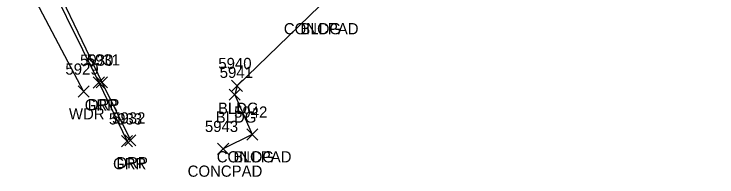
# Model space of a CAD drawing. Extents: x 1618146 to 1620418, y 640749 to 641927.
# Drawn here: x 1619963.1 to 1620088.9, y 641107.6 to 641136.7 of the extents above; entities that cross this region are included whole.
import ezdxf

# ---------------------------------------------------------------- set-up
doc = ezdxf.new("R2010")
doc.units = 0
for name, color, linetype in [('L_A', 7, 'Continuous'), ('L_I', 7, 'Continuous'), ('L_TIC', 7, 'Continuous'), ('LAWA', 7, 'Continuous'), ('LBC', 7, 'Continuous'), ('LS', 7, 'Continuous'), ('R_A', 7, 'Continuous'), ('R_I', 7, 'Continuous'), ('R_TIC', 7, 'Continuous'), ('RDP', 7, 'Continuous'), ('RGR', 7, 'Continuous')]:
    doc.layers.add(name, color=color, linetype=linetype)

msp = doc.modelspace()

# ---------------------------------------------------------------- linework, layer by layer
at = {"layer": 'L_TIC'}
for points in [[(1620001.99, 641122.9), (1620003.99, 641124.9)], [(1620003.99, 641122.9), (1620001.99, 641124.9)], [(1619974.53, 641121.9), (1619976.53, 641123.9)], [(1619976.53, 641121.9), (1619974.53, 641123.9)], [(1620001.58, 641121.32), (1620003.58, 641123.32)], [(1620003.58, 641121.32), (1620001.58, 641123.32)], [(1620004.73, 641114.22), (1620006.73, 641116.22)], [(1620006.73, 641114.22), (1620004.73, 641116.22)], [(1620004.73, 641114.22), (1620006.73, 641116.22)], [(1620006.73, 641114.22), (1620004.73, 641116.22)], [(1619999.5, 641111.66), (1620001.5, 641113.66)], [(1620001.5, 641111.66), (1619999.5, 641113.66)]]:
    msp.add_lwpolyline(points, dxfattribs=at)
at = {"layer": 'LAWA'}
msp.add_lwpolyline([(1620011.76, 641198.79), (1619992.67, 641182.34), (1619977.79, 641170.88), (1619968.52, 641161.58), (1619963.08, 641155.85), (1619963.66, 641145.43), (1619975.53, 641122.9)], dxfattribs=at)
at = {"layer": 'LBC'}
msp.add_lwpolyline([(1620182.25, 641113.36), (1620138.87, 641158.88), (1620119.63, 641179.08), (1620099.14, 641200.68), (1620061.44, 641164.75), (1620044.43, 641182.84), (1620044.17, 641182.77), (1620022.6, 641162.29), (1620014.93, 641155.19), (1620024.72, 641144.88), (1620017.73, 641138.11), (1620002.99, 641123.9), (1620002.58, 641122.32), (1620005.73, 641115.22)], dxfattribs=at)
at = {"layer": 'LS'}
msp.add_lwpolyline([(1620005.73, 641115.22), (1620000.5, 641112.66)], dxfattribs=at)
at = {"layer": 'R_TIC'}
for points in [[(1619977.24, 641123.49), (1619979.24, 641125.49)], [(1619979.24, 641123.49), (1619977.24, 641125.49)], [(1619977.8, 641123.54), (1619979.8, 641125.54)], [(1619979.8, 641123.54), (1619977.8, 641125.54)], [(1619982.31, 641113), (1619984.31, 641115)], [(1619984.31, 641113), (1619982.31, 641115)], [(1619982.9, 641113.17), (1619984.9, 641115.17)], [(1619984.9, 641113.17), (1619982.9, 641115.17)]]:
    msp.add_lwpolyline(points, dxfattribs=at)
at = {"layer": 'RDP'}
msp.add_lwpolyline([(1620043.03, 641194.19), (1620044.89, 641206.84), (1620037.07, 641211.43), (1620013.61, 641193.09), (1619994.36, 641179.67), (1619979.1, 641167.97), (1619969.08, 641160.78), (1619967.43, 641155.41), (1619967.4, 641148.34), (1619978.8, 641124.54), (1619983.9, 641114.17)], dxfattribs=at)
at = {"layer": 'RGR'}
msp.add_lwpolyline([(1620036.71, 641213.17), (1620026.73, 641206.23), (1620011.86, 641194.68), (1619993.66, 641180.69), (1619978.56, 641168.86), (1619968.76, 641161.75), (1619965.7, 641155.69), (1619966.63, 641148), (1619978.24, 641124.49), (1619983.31, 641114)], dxfattribs=at)

# ---------------------------------------------------------------- texts
at = {"layer": 'L_A'}
for s, p in [('CONCPAD', (1620011.37, 641133.11)), ('BLDG', (1620014.32, 641133.11)), ('BLDG', (1619999.58, 641118.9)), ('WDR', (1619972.9, 641117.9)), ('BLDG', (1619999.17, 641117.32)), ('CONCPAD', (1619999.37, 641110.22)), ('BLDG', (1620002.32, 641110.22)), ('CONCPAD', (1619994.15, 641107.66))]:
    msp.add_text(s, height=2, dxfattribs=at).set_placement(p)
at = {"layer": 'L_I'}
for s, p in [('5929', (1619972.27, 641125.9)), ('5940', (1619999.64, 641126.9)), ('5941', (1619999.89, 641125.32)), ('5942', (1620002.47, 641118.22)), ('5942', (1620002.47, 641118.22)), ('5943', (1619997.24, 641115.66))]:
    msp.add_text(s, height=2, dxfattribs=at).set_placement(p)
at = {"layer": 'R_A'}
for s, p in [('GRR', (1619975.73, 641119.49)), ('DRP', (1619976.28, 641119.54)), ('GRR', (1619980.8, 641109)), ('DRP', (1619981.39, 641109.17))]:
    msp.add_text(s, height=2, dxfattribs=at).set_placement(p)
at = {"layer": 'R_I'}
for s, p in [('5930', (1619974.9, 641127.49)), ('5931', (1619976.1, 641127.54)), ('5932', (1619980.64, 641117.17)), ('5933', (1619980.05, 641117))]:
    msp.add_text(s, height=2, dxfattribs=at).set_placement(p)

doc.saveas('drawing.dxf')
